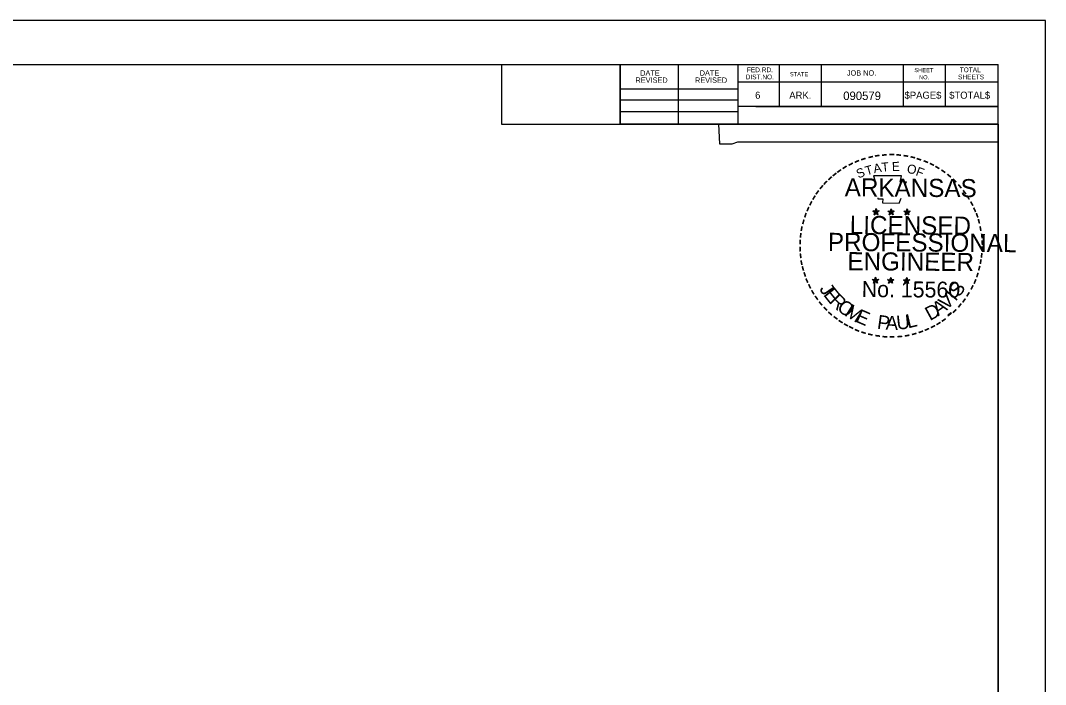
# Model space of a CAD drawing. Extents: x -1.6 to 32.4, y -0.7 to 21.3.
# Drawn here: x 15.42 to 32.4, y 10.27 to 21.27 of the extents above; entities that cross this region are included whole.
import ezdxf

# ---------------------------------------------------------------- set-up
doc = ezdxf.new("R2010")
doc.units = 0
for name, color, linetype in [('Level 1', 7, 'Continuous'), ('Level 49', 7, 'Continuous'), ('Level 62', 7, 'Continuous'), ('Level 63', 7, 'Continuous'), ('R_Border', 7, 'Continuous')]:
    doc.layers.add(name, color=color, linetype=linetype)

msp = doc.modelspace()

# ---------------------------------------------------------------- linework, layer by layer
at = {"layer": 'Level 1'}
for p, q in [((-0.001, 20.545), (31.617, 20.545)), ((25.353, 19.557), (25.353, 20.545)), ((26.321, 19.557), (26.321, 20.545)), ((27.307, 20.545), (27.307, 19.557)), ((27.991, 20.545), (27.991, 19.851)), ((28.685, 20.545), (28.685, 19.851)), ((30.043, 20.545), (30.043, 19.851)), ((30.737, 20.545), (30.737, 19.851)), ((31.617, -0.001), (31.617, 20.545)), ((31.617, 20.251), (27.307, 20.251)), ((31.617, 20.253), (31.617, 20.253)), ((25.353, 20.143), (27.307, 20.143)), ((25.353, 19.957), (27.307, 19.957)), ((25.353, 19.763), (27.307, 19.763)), ((31.617, 19.851), (27.307, 19.851)), ((27.603, 19.851), (31.617, 19.851)), ((31.617, 19.557), (25.353, 19.557))]:
    msp.add_line(p, q, dxfattribs=at)
msp.add_lwpolyline([(-0.001, 20.545), (25.353, 20.545), (25.353, 19.557), (27.307, 19.557), (27.307, 19.557), (31.617, 19.557), (31.617, 8.293), (-0.001, 8.293)], close=True, dxfattribs=at)
at = {"layer": 'Level 49'}
for p, q in [((29.54, 18.118), (29.594, 18.101)), ((29.54, 18.118), (29.579, 18.116)), ((29.54, 18.118), (29.579, 18.114)), ((29.54, 18.118), (29.576, 18.108)), ((29.54, 18.118), (29.576, 18.103)), ((29.54, 18.118), (29.576, 18.101)), ((29.54, 18.118), (29.576, 18.095)), ((29.563, 18.056), (29.594, 18.101)), ((29.563, 18.056), (29.576, 18.099)), ((29.563, 18.056), (29.579, 18.094)), ((29.563, 18.056), (29.581, 18.092)), ((29.563, 18.056), (29.587, 18.088)), ((29.563, 18.056), (29.594, 18.088)), ((29.563, 18.056), (29.594, 18.084)), ((29.594, 18.158), (29.587, 18.118)), ((29.594, 18.158), (29.587, 18.121)), ((29.594, 18.158), (29.59, 18.121)), ((29.594, 18.101), (29.594, 18.158)), ((29.594, 18.158), (29.603, 18.118)), ((29.594, 18.158), (29.601, 18.121)), ((29.594, 18.158), (29.596, 18.121)), ((29.646, 18.118), (29.594, 18.101)), ((29.626, 18.055), (29.594, 18.101)), ((29.626, 18.055), (29.594, 18.088)), ((29.626, 18.055), (29.594, 18.084)), ((29.646, 18.118), (29.598, 18.114)), ((29.626, 18.055), (29.598, 18.088)), ((29.646, 18.118), (29.603, 18.11)), ((29.646, 18.118), (29.603, 18.106)), ((29.626, 18.055), (29.603, 18.099)), ((29.626, 18.055), (29.603, 18.094)), ((29.626, 18.055), (29.609, 18.101)), ((29.646, 18.118), (29.611, 18.106)), ((29.646, 18.118), (29.616, 18.103)), ((29.646, 18.118), (29.618, 18.101)), ((29.79, 18.116), (29.844, 18.101)), ((29.79, 18.116), (29.829, 18.114)), ((29.79, 18.116), (29.829, 18.11)), ((29.79, 18.116), (29.829, 18.108)), ((29.79, 18.116), (29.827, 18.101)), ((29.79, 18.116), (29.827, 18.099)), ((29.79, 18.116), (29.827, 18.094)), ((29.813, 18.055), (29.844, 18.101)), ((29.813, 18.055), (29.829, 18.095)), ((29.813, 18.055), (29.829, 18.094)), ((29.813, 18.055), (29.831, 18.092)), ((29.813, 18.055), (29.837, 18.086)), ((29.813, 18.055), (29.844, 18.086)), ((29.813, 18.055), (29.844, 18.084)), ((29.844, 18.155), (29.837, 18.116)), ((29.844, 18.155), (29.837, 18.118)), ((29.844, 18.155), (29.839, 18.118)), ((29.844, 18.101), (29.844, 18.155)), ((29.844, 18.155), (29.853, 18.116)), ((29.844, 18.155), (29.852, 18.118)), ((29.844, 18.155), (29.846, 18.118)), ((29.896, 18.116), (29.844, 18.101)), ((29.876, 18.055), (29.844, 18.101)), ((29.876, 18.055), (29.844, 18.086)), ((29.876, 18.055), (29.844, 18.084)), ((29.896, 18.116), (29.85, 18.114)), ((29.876, 18.055), (29.85, 18.086)), ((29.896, 18.116), (29.853, 18.108)), ((29.896, 18.116), (29.853, 18.106)), ((29.876, 18.055), (29.853, 18.099)), ((29.876, 18.055), (29.853, 18.092)), ((29.876, 18.055), (29.859, 18.099)), ((29.896, 18.116), (29.861, 18.103)), ((29.896, 18.116), (29.866, 18.101)), ((29.896, 18.116), (29.868, 18.099)), ((30.055, 18.114), (30.109, 18.095)), ((30.055, 18.114), (30.098, 18.108)), ((30.055, 18.114), (30.094, 18.106)), ((30.055, 18.114), (30.094, 18.103)), ((30.055, 18.114), (30.092, 18.099)), ((30.055, 18.114), (30.092, 18.094)), ((30.055, 18.114), (30.092, 18.094)), ((30.076, 18.053), (30.109, 18.095)), ((30.076, 18.053), (30.094, 18.094)), ((30.076, 18.053), (30.098, 18.088)), ((30.076, 18.053), (30.098, 18.086)), ((30.076, 18.053), (30.109, 18.086)), ((30.076, 18.053), (30.105, 18.084)), ((30.076, 18.053), (30.113, 18.079)), ((30.109, 18.151), (30.1, 18.116)), ((30.109, 18.151), (30.105, 18.114)), ((30.109, 18.151), (30.105, 18.114)), ((30.109, 18.095), (30.109, 18.151)), ((30.109, 18.151), (30.12, 18.114)), ((30.109, 18.151), (30.116, 18.114)), ((30.109, 18.151), (30.113, 18.114)), ((30.161, 18.114), (30.109, 18.095)), ((30.139, 18.053), (30.109, 18.095)), ((30.139, 18.053), (30.109, 18.086)), ((30.139, 18.053), (30.109, 18.079)), ((30.161, 18.114), (30.115, 18.108)), ((30.139, 18.053), (30.115, 18.084)), ((30.161, 18.114), (30.12, 18.106)), ((30.161, 18.114), (30.12, 18.101)), ((30.139, 18.053), (30.12, 18.094)), ((30.139, 18.053), (30.12, 18.088)), ((30.139, 18.053), (30.124, 18.094)), ((30.161, 18.114), (30.128, 18.099)), ((30.161, 18.114), (30.129, 18.099)), ((30.161, 18.114), (30.135, 18.095)), ((29.587, 17.021), (29.576, 16.984)), ((29.587, 17.021), (29.579, 16.98)), ((29.587, 17.021), (29.581, 16.98)), ((29.587, 16.964), (29.587, 17.021)), ((29.587, 17.021), (29.594, 16.98)), ((29.587, 17.021), (29.594, 16.98)), ((29.587, 17.021), (29.587, 16.98)), ((29.837, 17.017), (29.827, 16.98)), ((29.837, 17.017), (29.829, 16.98)), ((29.837, 17.017), (29.831, 16.98)), ((29.837, 16.964), (29.837, 17.017)), ((29.837, 17.017), (29.844, 16.978)), ((29.837, 17.017), (29.844, 16.978)), ((29.837, 17.017), (29.837, 16.98)), ((30.102, 17.015), (30.092, 16.976)), ((30.102, 17.015), (30.094, 16.976)), ((30.102, 17.015), (30.098, 16.976)), ((30.102, 16.958), (30.102, 17.015)), ((30.102, 17.015), (30.109, 16.976)), ((30.102, 17.015), (30.109, 16.976)), ((30.102, 17.015), (30.102, 16.976)), ((29.533, 16.98), (29.587, 16.964)), ((29.533, 16.98), (29.572, 16.978)), ((29.533, 16.98), (29.57, 16.973)), ((29.533, 16.98), (29.57, 16.973)), ((29.533, 16.98), (29.57, 16.965)), ((29.533, 16.98), (29.57, 16.964)), ((29.533, 16.98), (29.57, 16.962)), ((29.551, 16.923), (29.587, 16.964)), ((29.551, 16.923), (29.57, 16.964)), ((29.551, 16.923), (29.572, 16.956)), ((29.551, 16.923), (29.574, 16.956)), ((29.551, 16.923), (29.587, 16.954)), ((29.551, 16.923), (29.579, 16.951)), ((29.551, 16.923), (29.587, 16.949)), ((29.616, 16.919), (29.583, 16.949)), ((29.639, 16.98), (29.587, 16.964)), ((29.616, 16.919), (29.587, 16.964)), ((29.616, 16.919), (29.587, 16.951)), ((29.616, 16.919), (29.589, 16.951)), ((29.639, 16.98), (29.59, 16.978)), ((29.639, 16.98), (29.594, 16.973)), ((29.639, 16.98), (29.594, 16.971)), ((29.616, 16.919), (29.594, 16.964)), ((29.616, 16.919), (29.594, 16.956)), ((29.639, 16.98), (29.601, 16.969)), ((29.616, 16.919), (29.601, 16.964)), ((29.639, 16.98), (29.605, 16.965)), ((29.639, 16.98), (29.609, 16.964)), ((29.783, 16.98), (29.837, 16.964)), ((29.783, 16.98), (29.822, 16.976)), ((29.783, 16.98), (29.822, 16.973)), ((29.783, 16.98), (29.822, 16.971)), ((29.783, 16.98), (29.82, 16.965)), ((29.783, 16.98), (29.82, 16.962)), ((29.783, 16.98), (29.82, 16.958)), ((29.802, 16.919), (29.837, 16.964)), ((29.802, 16.919), (29.822, 16.962)), ((29.802, 16.919), (29.822, 16.954)), ((29.802, 16.919), (29.824, 16.954)), ((29.802, 16.919), (29.829, 16.951)), ((29.802, 16.919), (29.837, 16.951)), ((29.802, 16.919), (29.837, 16.947)), ((29.866, 16.919), (29.835, 16.947)), ((29.887, 16.978), (29.837, 16.964)), ((29.866, 16.919), (29.837, 16.964)), ((29.866, 16.919), (29.837, 16.951)), ((29.866, 16.919), (29.839, 16.951)), ((29.887, 16.978), (29.842, 16.978)), ((29.887, 16.978), (29.844, 16.971)), ((29.887, 16.978), (29.844, 16.971)), ((29.866, 16.919), (29.844, 16.962)), ((29.866, 16.919), (29.844, 16.956)), ((29.887, 16.978), (29.852, 16.965)), ((29.866, 16.919), (29.852, 16.962)), ((29.887, 16.978), (29.857, 16.964)), ((29.887, 16.978), (29.859, 16.962)), ((30.048, 16.976), (30.102, 16.958)), ((30.048, 16.976), (30.087, 16.973)), ((30.048, 16.976), (30.087, 16.969)), ((30.048, 16.976), (30.085, 16.965)), ((30.048, 16.976), (30.085, 16.962)), ((30.048, 16.976), (30.083, 16.958)), ((30.048, 16.976), (30.083, 16.954)), ((30.068, 16.915), (30.102, 16.958)), ((30.068, 16.915), (30.085, 16.958)), ((30.068, 16.915), (30.087, 16.951)), ((30.068, 16.915), (30.091, 16.951)), ((30.068, 16.915), (30.094, 16.947)), ((30.068, 16.915), (30.1, 16.947)), ((30.068, 16.915), (30.102, 16.943)), ((30.131, 16.915), (30.1, 16.947)), ((30.131, 16.915), (30.1, 16.943)), ((30.153, 16.976), (30.102, 16.958)), ((30.131, 16.915), (30.102, 16.958)), ((30.131, 16.915), (30.105, 16.947)), ((30.153, 16.976), (30.107, 16.973)), ((30.153, 16.976), (30.109, 16.969)), ((30.153, 16.976), (30.109, 16.965)), ((30.131, 16.915), (30.109, 16.951)), ((30.131, 16.915), (30.113, 16.958)), ((30.131, 16.915), (30.115, 16.958)), ((30.153, 16.976), (30.12, 16.964)), ((30.153, 16.976), (30.122, 16.958)), ((30.153, 16.976), (30.124, 16.958))]:
    msp.add_line(p, q, dxfattribs=at)
for points in [[(29.551, 18.701), (29.589, 18.575)], [(30.078, 18.558), (30.1, 18.603), (29.994, 18.597), (30.018, 18.697), (29.551, 18.701)], [(29.624, 18.336), (29.624, 18.321), (29.707, 18.32), (29.7, 18.251), (29.979, 18.249), (30.009, 18.327)], [(29.594, 18.158), (29.626, 18.055), (29.54, 18.118), (29.646, 18.118), (29.563, 18.056), (29.594, 18.158)], [(29.844, 18.155), (29.876, 18.055), (29.79, 18.116), (29.896, 18.116), (29.813, 18.055), (29.844, 18.155)], [(30.109, 18.151), (30.139, 18.053), (30.055, 18.114), (30.161, 18.114), (30.076, 18.053), (30.109, 18.151)], [(29.587, 17.021), (29.616, 16.919), (29.533, 16.98), (29.639, 16.98), (29.551, 16.923), (29.587, 17.021)], [(29.837, 17.017), (29.866, 16.919), (29.783, 16.98), (29.887, 16.978), (29.802, 16.919), (29.837, 17.017)], [(30.102, 17.015), (30.131, 16.915), (30.048, 16.976), (30.153, 16.976), (30.068, 16.915), (30.102, 17.015)], [(30.796, 16.374), (30.789, 16.399), (30.833, 16.436)], [(30.83, 16.441), (30.837, 16.419), (30.793, 16.38)], [(30.837, 16.423), (30.793, 16.384)], [(30.837, 16.419), (30.794, 16.382)]]:
    msp.add_lwpolyline(points, dxfattribs=at)
for centre, radius in [((29.595, 18.1), 0.0259), ((29.595, 18.1), 0.0234), ((29.595, 18.1), 0.0217), ((29.595, 18.1), 0.0199), ((29.595, 18.1), 0.0174), ((29.595, 18.1), 0.0161), ((29.595, 18.1), 0.0149), ((29.595, 18.1), 0.0128), ((29.595, 18.1), 0.0112), ((29.595, 18.1), 0.00933), ((29.595, 18.1), 0.00744), ((29.595, 18.1), 0.00555), ((29.595, 18.1), 0.00445), ((29.595, 18.1), 0.00216), ((29.845, 18.098), 0.0259), ((29.845, 18.098), 0.0234), ((29.845, 18.098), 0.0217), ((29.845, 18.098), 0.0199), ((29.845, 18.098), 0.0174), ((29.845, 18.098), 0.0161), ((29.845, 18.098), 0.0149), ((29.845, 18.098), 0.0128), ((29.845, 18.098), 0.0112), ((29.845, 18.098), 0.00933), ((29.845, 18.098), 0.00744), ((29.845, 18.098), 0.00555), ((29.845, 18.098), 0.00445), ((29.845, 18.098), 0.00216), ((30.111, 18.095), 0.0259), ((30.111, 18.095), 0.0234), ((30.111, 18.095), 0.0217), ((30.111, 18.095), 0.0199), ((30.111, 18.095), 0.0174), ((30.111, 18.095), 0.0161), ((30.111, 18.095), 0.0149), ((30.111, 18.095), 0.0128), ((30.111, 18.095), 0.0112), ((30.111, 18.095), 0.00933), ((30.111, 18.095), 0.00744), ((30.111, 18.095), 0.00555), ((30.111, 18.095), 0.00445), ((30.111, 18.095), 0.00216), ((29.586, 16.963), 0.0259), ((29.586, 16.963), 0.0234), ((29.586, 16.963), 0.0217), ((29.586, 16.963), 0.0199), ((29.837, 16.962), 0.0259), ((29.837, 16.962), 0.0234), ((29.837, 16.962), 0.0217), ((30.102, 16.958), 0.0259), ((29.586, 16.963), 0.0174), ((29.586, 16.963), 0.0161), ((29.586, 16.963), 0.0149), ((29.586, 16.963), 0.0128), ((29.586, 16.963), 0.0112), ((29.586, 16.963), 0.00933), ((29.586, 16.963), 0.00744), ((29.586, 16.963), 0.00555), ((29.586, 16.963), 0.00445), ((29.586, 16.963), 0.00216), ((29.837, 16.962), 0.0199), ((29.837, 16.962), 0.0174), ((29.837, 16.962), 0.0161), ((29.837, 16.962), 0.0149), ((29.837, 16.962), 0.0128), ((29.837, 16.962), 0.0112), ((29.837, 16.962), 0.00933), ((29.837, 16.962), 0.00744), ((29.837, 16.962), 0.00555), ((29.837, 16.962), 0.00445), ((29.837, 16.962), 0.00216), ((30.102, 16.958), 0.0234), ((30.102, 16.958), 0.0217), ((30.102, 16.958), 0.0199), ((30.102, 16.958), 0.0174), ((30.102, 16.958), 0.0161), ((30.102, 16.958), 0.0149), ((30.102, 16.958), 0.0128), ((30.102, 16.958), 0.0112), ((30.102, 16.958), 0.00933), ((30.102, 16.958), 0.00744), ((30.102, 16.958), 0.00555), ((30.102, 16.958), 0.00445), ((30.102, 16.958), 0.00216)]:
    msp.add_circle(centre, radius, dxfattribs=at)
at = {"layer": 'Level 62'}
msp.add_lwpolyline([(-0.001, 20.545), (23.391, 20.545), (23.391, 20.545), (23.391, 19.557), (23.391, 19.557), (26.987, 19.557), (26.999, 19.232), (27.211, 19.232), (27.307, 19.265), (31.617, 19.265), (31.617, 8.293), (-0.001, 8.293)], close=True, dxfattribs=at)
at = {"layer": 'Level 63'}
msp.add_lwpolyline([(-1.598, -0.727), (32.402, -0.727), (32.402, 21.273), (-1.598, 21.273)], close=True, dxfattribs=at)

# ---------------------------------------------------------------- texts
at = {"layer": 'Level 1'}
for s, height, p in [('DATE', 0.0879, (25.687, 20.359)), ('DATE', 0.0879, (26.673, 20.359)), ('FED.RD.', 0.0782, (27.455, 20.417)), ('STATE', 0.0684, (28.167, 20.349)), ('JOB NO.', 0.0879, (29.112, 20.36)), ('SHEET', 0.0684, (30.229, 20.417)), ('TOTAL', 0.0782, (30.981, 20.417)), ('REVISED', 0.0879, (25.609, 20.241)), ('REVISED', 0.0879, (26.595, 20.241)), ('DIST.NO.', 0.0782, (27.435, 20.299)), ('NO.', 0.0684, (30.307, 20.299)), ('SHEETS', 0.0782, (30.953, 20.299)), ('6', 0.117, (27.591, 19.977)), ('ARK.', 0.1172, (28.157, 19.977)), ('090579', 0.14, (29.051, 19.956)), ('$PAGE$', 0.1172, (30.067, 19.977)), ('$TOTAL$', 0.1172, (30.806, 19.977))]:
    msp.add_text(s, height=height, dxfattribs=at).set_placement(p)
at = {"layer": 'Level 49'}
for s, height, rotation, p in [('-', 0.24, 13.2326, (29.476, 18.909)), ('-', 0.24, 9.8217, (29.576, 18.933)), ('-', 0.24, 5.4992, (29.687, 18.948)), ('-', 0.24, 359.7886, (29.802, 18.959)), ('-', 0.24, 357.3454, (29.913, 18.955)), ('-', 0.24, 351.7641, (30.022, 18.946)), ('-', 0.24, 346.8073, (30.131, 18.929)), ('-', 0.24, 33.666, (29.081, 18.733)), ('-', 0.24, 28.3942, (29.172, 18.786)), ('-', 0.24, 23.9096, (29.266, 18.833)), ('-', 0.24, 18.7785, (29.363, 18.873)), ('T', 0.15, 16.006, (29.438, 18.705)), ('A', 0.15, 10.8156, (29.564, 18.742)), ('T', 0.15, 5.6252, (29.692, 18.766)), ('E', 0.15, 0.4347, (29.857, 18.781)), ('O', 0.15, 350.0539, (30.098, 18.749)), ('-', 0.24, 341.9386, (30.226, 18.903)), ('-', 0.24, 337.4575, (30.335, 18.87)), ('-', 0.24, 333.7235, (30.431, 18.831)), ('-', 0.24, 329.2433, (30.517, 18.786)), ('-', 0.24, 42.5646, (28.857, 18.555)), ('-', 0.24, 38.5531, (28.923, 18.616)), ('-', 0.24, 35.8341, (28.994, 18.673)), ('S', 0.15, 21.1964, (29.301, 18.655)), ('F', 0.15, 339.6731, (30.241, 18.712)), ('-', 0.24, 325.4651, (30.613, 18.729)), ('-', 0.24, 320.1321, (30.704, 18.666)), ('-', 0.24, 50.2166, (28.727, 18.412)), ('-', 0.24, 48.0255, (28.788, 18.484)), ('ARKANSAS', 0.3002, 359.6024, (29.075, 18.36)), ('-', 0.24, 315.181, (30.794, 18.592)), ('-', 0.24, 309.4821, (30.878, 18.508)), ('-', 0.24, 57.673, (28.616, 18.245)), ('-', 0.24, 53.8349, (28.664, 18.327)), ('-', 0.24, 306.2546, (30.954, 18.418)), ('-', 0.21, 303.2777, (31.028, 18.331)), ('-', 0.24, 67.3767, (28.531, 18.064)), ('-', 0.24, 62.4738, (28.57, 18.155)), ('-', 0.24, 299.2708, (31.074, 18.24)), ('-', 0.24, 294.2652, (31.122, 18.147)), ('-', 0.24, 71.9969, (28.496, 17.969)), ('LICENSED', 0.3002, 359.6024, (29.159, 17.738)), ('-', 0.24, 290.1752, (31.163, 18.064)), ('-', 0.24, 80.8037, (28.444, 17.756)), ('-', 0.24, 75.0634, (28.466, 17.862)), ('-', 0.24, 284.7257, (31.195, 17.975)), ('-', 0.24, 280.1517, (31.224, 17.862)), ('-', 0.24, 84.7887, (28.433, 17.653)), ('PROFESSIONAL', 0.30016, 359.6024, (28.796, 17.456)), ('-', 0.24, 276.1986, (31.25, 17.747)), ('-', 0.24, 93.7983, (28.433, 17.438)), ('-', 0.24, 88.6646, (28.429, 17.547)), ('-', 0.24, 273.9325, (31.258, 17.638)), ('-', 0.24, 269.5431, (31.261, 17.545)), ('-', 0.24, 98.5503, (28.444, 17.336)), ('ENGINEER', 0.3002, 359.6024, (29.12, 17.136)), ('-', 0.24, 263.1196, (31.258, 17.445)), ('-', 0.24, 101.3173, (28.46, 17.227)), ('-', 0.24, 105.0602, (28.486, 17.138)), ('-', 0.24, 255.365, (31.228, 17.245)), ('-', 0.24, 260.5977, (31.245, 17.347)), ('-', 0.24, 108.6898, (28.518, 17.045)), ('-', 0.24, 113.6667, (28.555, 16.952)), ('-', 0.24, 247.4911, (31.169, 17.034)), ('-', 0.24, 252.4705, (31.202, 17.136)), ('-', 0.24, 115.3313, (28.601, 16.86)), ('J', 0.231, 303.9209, (28.647, 16.824)), ('E', 0.231, 308.618, (28.712, 16.728)), ('No. 15560', 0.2641, 359.6024, (29.357, 16.692)), ('S', 0.231, 53.5227, (30.967, 16.677)), ('-', 0.24, 244.2221, (31.126, 16.941)), ('-', 0.24, 120.0495, (28.653, 16.771)), ('-', 0.24, 125.4958, (28.714, 16.688)), ('R', 0.231, 314.7784, (28.809, 16.609)), ('V', 0.231, 41.4844, (30.756, 16.466)), ('I', 0.231, 49.9999, (30.91, 16.611)), ('-', 0.24, 233.4476, (31.009, 16.732)), ('-', 0.24, 238.6736, (31.067, 16.83)), ('-', 0.24, 130.3205, (28.781, 16.604)), ('-', 0.24, 133.8262, (28.859, 16.523)), ('O', 0.231, 321.6761, (28.932, 16.49)), ('M', 0.231, 328.1357, (29.059, 16.393)), ('E', 0.231, 336.4966, (29.238, 16.289)), ('D', 0.231, 28.5809, (30.487, 16.293)), ('A', 0.231, 34.8903, (30.624, 16.37)), ('-', 0.24, 225.3677, (30.869, 16.563)), ('-', 0.24, 233.4476, (30.939, 16.65)), ('-', 0.24, 138.5362, (28.935, 16.452)), ('-', 0.24, 144.2487, (29.022, 16.391)), ('-', 0.24, 147.6922, (29.103, 16.334)), ('P', 0.231, 351.9783, (29.603, 16.17)), ('A', 0.231, 357.9896, (29.751, 16.151)), ('U', 0.231, 5.7635, (29.943, 16.149)), ('L', 0.231, 13.0992, (30.124, 16.172)), ('-', 0.24, 215.3387, (30.706, 16.417)), ('-', 0.24, 151.1728, (29.188, 16.286)), ('-', 0.24, 154.2026, (29.27, 16.247)), ('-', 0.24, 158.1636, (29.363, 16.206)), ('-', 0.24, 200.3208, (30.355, 16.221)), ('-', 0.24, 203.854, (30.448, 16.261)), ('-', 0.24, 206.9592, (30.543, 16.308)), ('-', 0.24, 211.8515, (30.626, 16.36)), ('-', 0.24, 162.4007, (29.466, 16.174)), ('-', 0.24, 167.1579, (29.572, 16.15)), ('-', 0.24, 172.7179, (29.687, 16.134)), ('-', 0.24, 176.1207, (29.8, 16.123)), ('-', 0.24, 181.1942, (29.911, 16.126)), ('-', 0.24, 185.4191, (30.033, 16.135)), ('-', 0.24, 190.8882, (30.144, 16.154)), ('-', 0.24, 195.0767, (30.254, 16.184))]:
    msp.add_text(s, height=height, rotation=rotation, dxfattribs=at).set_placement(p)
at = {"layer": 'R_Border'}
msp.add_text('JOB NO.', height=0.0879, dxfattribs=at).set_placement((29.112, 20.36))

doc.saveas('drawing.dxf')
